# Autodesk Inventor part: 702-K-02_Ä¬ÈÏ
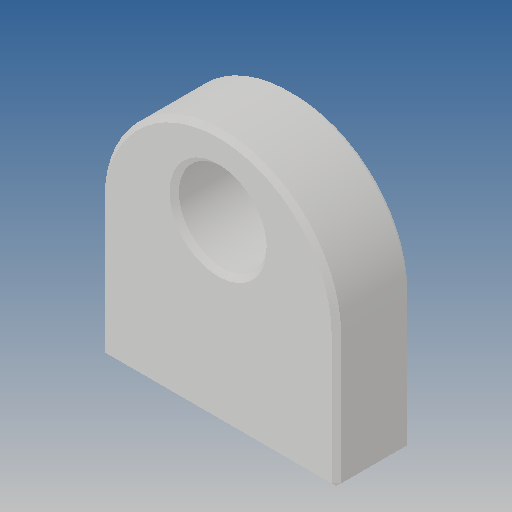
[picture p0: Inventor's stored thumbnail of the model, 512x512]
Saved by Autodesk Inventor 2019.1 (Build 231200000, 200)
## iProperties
Created: 2010-06
Part Number: 702-K-02_Ä¬ÈÏ
Material: Ogólny
Document SubType Name: Modeling
Designer: CADENGINEERING4
Density: 1 g/cm^3
Appearance: Domyślna
Author: CADENGINEERING4
Revision Number: ÈÎºÎ
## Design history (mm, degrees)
feature "NONE"
node "Bryła1"
